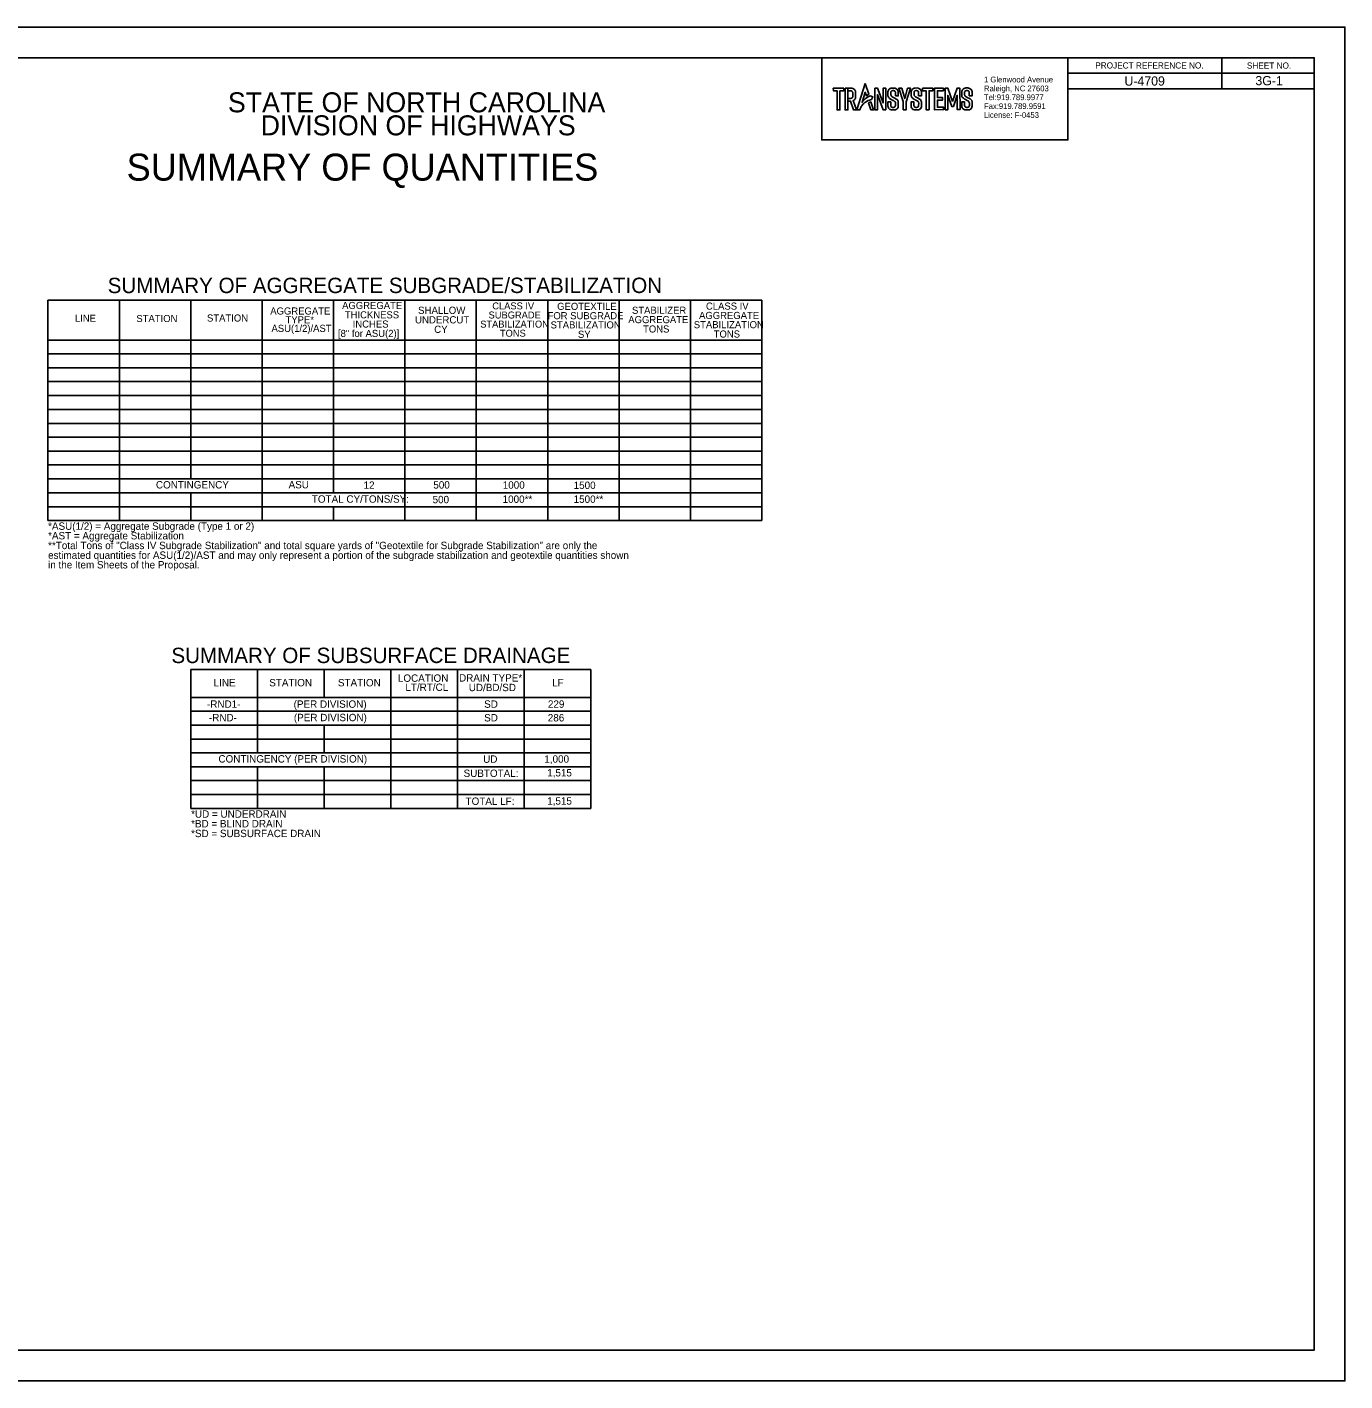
# Model space of a CAD drawing. Extents: x 573680 to 575380, y -54660 to -53560.
# Drawn here: x 574309 to 575380, y -54660 to -53560 of the extents above; entities that cross this region are included whole.
import ezdxf

# ---------------------------------------------------------------- set-up
doc = ezdxf.new("R2010")
doc.units = 0
for name, color, linetype in [('Old_Level_2', 7, 'Continuous'), ('Old_Level_58', 7, 'Continuous'), ('Prop Dimension Text', 7, 'Continuous'), ('Sheet Data Field CELL', 7, 'Continuous'), ('Sheet Plan And Profile CELL', 7, 'Continuous'), ('Sheet Plot Border Outside CELL', 7, 'Continuous'), ('Sheet Summary CELL', 7, 'Continuous'), ('Sheet Summary Combination CELL', 7, 'Continuous'), ('Sheet Summary Combination Grid CELL', 7, 'Continuous')]:
    doc.layers.add(name, color=color, linetype=linetype)

msp = doc.modelspace()

# ---------------------------------------------------------------- linework, layer by layer
at = {"layer": 'Old_Level_58'}
msp.add_lwpolyline([(574954.8, -53584.7), (575154.8, -53584.7), (575154.8, -53651.4), (574954.8, -53651.4)], close=True, dxfattribs=at)
at = {"layer": 'Sheet Plan And Profile CELL'}
for p, q in [((575279.9, -53584.8), (575279.9, -53609.8)), ((575154.8, -53597.3), (575354.9, -53597.3))]:
    msp.add_line(p, q, dxfattribs=at)
msp.add_lwpolyline([(575354.9, -53584.7), (573854.9, -53584.7), (573854.9, -54634.7), (575354.9, -54634.7)], close=True, dxfattribs=at)
at = {"layer": 'Sheet Plot Border Outside CELL'}
msp.add_lwpolyline([(573679.9, -54659.7), (575379.9, -54659.7), (575379.9, -53559.7), (573679.9, -53559.7)], close=True, dxfattribs=at)
at = {"layer": 'Sheet Summary CELL'}
for p, q in [((575279.9, -53584.8), (575279.9, -53609.8)), ((575154.8, -53597.3), (575354.9, -53597.3)), ((574604.5, -53673.5), (574604.5, -53673.5))]:
    msp.add_line(p, q, dxfattribs=at)
msp.add_lwpolyline([(575154.8, -53584.7), (575354.9, -53584.7), (575354.9, -53609.8), (575154.8, -53609.8)], close=True, dxfattribs=at)
at = {"layer": 'Sheet Summary Combination CELL'}
for p, q in [((574569.8, -54081.8), (574569.8, -54081.8)), ((574575.4, -54081.9), (574575.4, -54081.9)), ((574583.6, -54081.7), (574583.6, -54081.7)), ((574588.6, -54081.8), (574588.6, -54081.8))]:
    msp.add_line(p, q, dxfattribs=at)
at = {"layer": 'Sheet Summary Combination Grid CELL'}
for p, q in [((574326.1, -53781.7), (574906.1, -53781.7)), ((574326.1, -53781.7), (574326.1, -53960.7)), ((574384.1, -53781.7), (574384.1, -53960.7)), ((574442.1, -53781.7), (574442.1, -53926.8)), ((574500.1, -53781.7), (574500.1, -53960.7)), ((574558.1, -53781.7), (574558.1, -53938.1)), ((574616.1, -53781.7), (574616.1, -53960.7)), ((574674.1, -53781.7), (574674.1, -53960.7)), ((574732.1, -53781.7), (574732.1, -53960.7)), ((574790.1, -53781.7), (574790.1, -53960.7)), ((574848.1, -53781.7), (574848.1, -53960.7)), ((574906.1, -53781.7), (574906.1, -53960.7)), ((574326.1, -53814), (574906.1, -53814)), ((574326.1, -53825.3), (574906.1, -53825.3)), ((574326.1, -53836.6), (574906.1, -53836.6)), ((574326.1, -53847.8), (574906.1, -53847.8)), ((574326.1, -53859.1), (574580, -53859.1)), ((574326.1, -53859.1), (574906.1, -53859.1)), ((574326.1, -53870.4), (574906.1, -53870.4)), ((574326.1, -53881.7), (574906.1, -53881.7)), ((574326.1, -53893), (574906.1, -53893)), ((574326.1, -53904.3), (574906.1, -53904.3)), ((574326.1, -53915.5), (574906.1, -53915.5)), ((574326.1, -53926.8), (574906.1, -53926.8)), ((574326.1, -53938.1), (574906.1, -53938.1)), ((574442.1, -53938.1), (574442.1, -53960.7)), ((574326.1, -53949.4), (574906.1, -53949.4)), ((574558.1, -53949.4), (574558.1, -53960.7)), ((574326.1, -53960.7), (574906.1, -53960.7)), ((574442.3, -54081.8), (574767.2, -54081.8)), ((574442.3, -54081.8), (574442.3, -54194.6)), ((574496.4, -54081.8), (574496.4, -54149.5)), ((574550.6, -54081.8), (574550.6, -54104.4)), ((574604.7, -54081.8), (574604.7, -54194.6)), ((574658.9, -54081.8), (574658.9, -54194.6)), ((574713, -54081.8), (574713, -54194.6)), ((574767.2, -54081.8), (574767.2, -54194.6)), ((574442.3, -54104.4), (574767.2, -54104.4)), ((574442.3, -54115.6), (574767.2, -54115.6)), ((574442.3, -54126.9), (574767.2, -54126.9)), ((574550.6, -54126.9), (574550.6, -54149.5)), ((574442.3, -54138.2), (574767.2, -54138.2)), ((574442.3, -54149.5), (574696.2, -54149.5)), ((574442.3, -54149.5), (574767.2, -54149.5)), ((574442.3, -54149.5), (574767.2, -54149.5)), ((574442.3, -54160.8), (574767.2, -54160.8)), ((574496.4, -54160.8), (574496.4, -54194.6)), ((574550.6, -54160.8), (574550.6, -54194.6)), ((574550.6, -54160.8), (574550.6, -54194.6)), ((574442.3, -54172), (574767.2, -54172)), ((574442.3, -54183.3), (574767.2, -54183.3)), ((574442.3, -54194.6), (574767.2, -54194.6))]:
    msp.add_line(p, q, dxfattribs=at)
for points in [[(574964.1, -53609.5), (574972.6, -53609.5), (574972.6, -53611.6), (574969.5, -53611.6), (574969.5, -53627), (574967.2, -53627), (574967.2, -53611.5), (574964.2, -53611.5)], [(574973.8, -53609.5), (574976.1, -53609.5), (574976.1, -53627.1), (574973.8, -53627.1)], [(574976.1, -53611.6), (574978.5, -53611.6), (574978.8, -53611.6), (574979.2, -53611.8), (574979.5, -53612), (574979.7, -53612.3), (574979.9, -53612.6), (574980, -53612.9), (574980, -53613.5), (574980, -53615.9), (574980, -53616.3), (574979.9, -53616.7), (574979.7, -53617), (574979.5, -53617.3), (574979.3, -53617.5), (574978.9, -53617.6), (574978.5, -53617.7), (574978.2, -53617.7), (574976.1, -53617.7), (574976.1, -53619.8), (574978.2, -53619.8), (574980.6, -53627), (574983, -53627), (574980.3, -53619.4), (574980.7, -53619.3), (574981.3, -53618.9), (574981.7, -53618.4), (574982.1, -53617.7), (574982.3, -53617.1), (574982.3, -53616.9), (574982.3, -53612.3), (574982.1, -53611.6), (574981.8, -53610.9), (574981.4, -53610.4), (574980.7, -53610), (574980, -53609.7), (574979.3, -53609.5), (574978.9, -53609.5), (574976.1, -53609.5)], [(574990.1, -53605.6), (574983.4, -53627), (574985.7, -53627), (574986, -53626.1), (574986.6, -53625), (574986.9, -53624.3), (574987.3, -53623.8), (574987.8, -53623), (574988.1, -53622.6), (574988.5, -53622.2), (574988.9, -53621.8), (574989.4, -53621.3), (574989.8, -53621), (574990.2, -53620.7), (574990.8, -53620.4), (574991.2, -53620.1), (574992.5, -53619.5), (574993.5, -53619.1), (574995.1, -53618.5), (574996.2, -53616.4), (574994.1, -53615.5), (574992.4, -53616.3), (574991.1, -53617.2), (574990.1, -53618), (574989.6, -53618.5), (574989, -53619), (574988.5, -53619.6), (574988.1, -53620), (574987.7, -53620.7), (574987.5, -53621), (574990.1, -53612.7), (574991.1, -53615.5), (574993, -53614.3)], [(574997.9, -53609.5), (574997.9, -53626.9), (575000.1, -53626.9), (575000.1, -53614.6), (575004.6, -53626.9), (575006.8, -53626.9), (575006.8, -53609.4), (575004.6, -53609.4), (575004.6, -53621.4), (575000.2, -53609.5)], [(575014.6, -53615.6), (575016.9, -53615.6), (575016.9, -53612.2), (575016.7, -53611.4), (575016.4, -53610.9), (575016.1, -53610.5), (575015.7, -53610.1), (575015.3, -53609.8), (575014.9, -53609.7), (575014.9, -53609.7), (575014.4, -53609.5), (575013.9, -53609.3), (575013.6, -53609.3), (575011.9, -53609.3), (575011.3, -53609.4), (575010.9, -53609.5), (575010.4, -53609.7), (575010, -53609.9), (575009.6, -53610.2), (575009.3, -53610.5), (575009.1, -53610.9), (575008.9, -53611.3), (575008.6, -53612), (575008.6, -53612.5), (575008.6, -53615.7), (575008.7, -53616.1), (575008.9, -53616.6), (575009.2, -53617), (575009.5, -53617.3), (575009.9, -53617.7), (575010.4, -53618), (575010.7, -53618.3), (575011.2, -53618.5), (575011.7, -53618.7), (575012, -53619), (575012.5, -53619.3), (575013, -53619.5), (575013.4, -53619.7), (575013.9, -53620.1), (575014.2, -53620.3), (575014.4, -53620.6), (575014.6, -53621.1), (575014.7, -53621.4), (575014.6, -53623.6), (575014.5, -53624.1), (575014.2, -53624.5), (575013.9, -53624.8), (575013.6, -53625), (575013.2, -53625), (575012.3, -53625.1), (575011.9, -53625), (575011.6, -53624.8), (575011.3, -53624.6), (575011.1, -53624.2), (575011, -53623.9), (575010.9, -53623.6), (575010.8, -53620.5), (575008.5, -53620.6), (575008.5, -53624.3), (575008.7, -53624.5), (575008.9, -53625.4), (575009.1, -53625.7), (575009.4, -53626), (575009.7, -53626.4), (575010, -53626.6), (575010.5, -53626.8), (575010.6, -53626.8), (575011.1, -53627), (575011.6, -53627.1), (575012, -53627.1), (575014.1, -53627.1), (575014.7, -53626.9), (575015.6, -53626.5), (575015.8, -53626.4), (575016.5, -53625.6), (575016.8, -53624.8), (575016.9, -53624.1), (575016.9, -53620.7), (575016.9, -53620.2), (575016.8, -53619.9), (575016.6, -53619.5), (575016, -53618.7), (575015.3, -53618.2), (575014.3, -53617.6), (575013.6, -53617.2), (575012.1, -53616.4), (575011.4, -53615.8), (575011.1, -53615.4), (575011, -53615.1), (575010.9, -53614.8), (575010.9, -53612.4), (575011.1, -53612.2), (575011.2, -53611.9), (575011.4, -53611.8), (575011.6, -53611.6), (575011.9, -53611.4), (575012.1, -53611.3), (575012.3, -53611.4), (575012.3, -53611.3), (575013.2, -53611.3), (575013.5, -53611.4), (575013.8, -53611.5), (575014.1, -53611.6), (575014.2, -53611.8), (575014.4, -53612.1), (575014.5, -53612.4), (575014.6, -53612.7), (575014.6, -53613)], [(575019.9, -53609.5), (575017.3, -53609.5), (575020.9, -53620.3), (575021, -53626.9), (575023.4, -53626.9), (575023.3, -53620.4), (575027, -53609.4), (575024.5, -53609.5), (575022.2, -53617.8)], [(575033.5, -53615.6), (575035.8, -53615.6), (575035.8, -53612.1), (575035.6, -53611.4), (575035.3, -53610.8), (575035, -53610.4), (575034.6, -53610.1), (575034.2, -53609.8), (575033.7, -53609.6), (575033.7, -53609.6), (575033.3, -53609.4), (575032.8, -53609.3), (575032.5, -53609.2), (575030.7, -53609.3), (575030.2, -53609.4), (575029.8, -53609.5), (575029.3, -53609.7), (575028.9, -53609.9), (575028.5, -53610.2), (575028.2, -53610.5), (575027.9, -53610.9), (575027.7, -53611.3), (575027.5, -53612), (575027.4, -53612.5), (575027.4, -53615.6), (575027.6, -53616.1), (575027.8, -53616.6), (575028.1, -53617), (575028.4, -53617.3), (575028.8, -53617.7), (575029.3, -53618), (575029.6, -53618.2), (575030, -53618.5), (575030.5, -53618.7), (575030.9, -53619), (575031.4, -53619.2), (575031.9, -53619.5), (575032.3, -53619.7), (575032.7, -53620), (575033.1, -53620.3), (575033.3, -53620.6), (575033.5, -53621.1), (575033.6, -53621.3), (575033.5, -53623.6), (575033.4, -53624.1), (575033.1, -53624.5), (575032.8, -53624.8), (575032.4, -53624.9), (575032.1, -53625), (575031.1, -53625), (575030.8, -53624.9), (575030.5, -53624.8), (575030.1, -53624.6), (575030, -53624.2), (575029.9, -53623.9), (575029.7, -53623.6), (575029.7, -53620.5), (575027.4, -53620.5), (575027.4, -53624.2), (575027.5, -53624.5), (575027.8, -53625.4), (575028, -53625.7), (575028.2, -53626), (575028.6, -53626.4), (575028.9, -53626.6), (575029.4, -53626.8), (575029.5, -53626.8), (575029.9, -53627), (575030.5, -53627.1), (575030.9, -53627.1), (575033, -53627), (575033.6, -53626.9), (575034.4, -53626.5), (575034.7, -53626.4), (575035.3, -53625.6), (575035.7, -53624.8), (575035.8, -53624.1), (575035.8, -53620.7), (575035.8, -53620.2), (575035.6, -53619.8), (575035.4, -53619.5), (575034.9, -53618.7), (575034.2, -53618.2), (575033.2, -53617.6), (575032.5, -53617.1), (575031, -53616.4), (575030.3, -53615.8), (575029.9, -53615.4), (575029.8, -53615.1), (575029.8, -53614.8), (575029.8, -53612.4), (575029.9, -53612.1), (575030.1, -53611.9), (575030.2, -53611.7), (575030.5, -53611.5), (575030.7, -53611.4), (575031, -53611.3), (575031.1, -53611.4), (575031.2, -53611.3), (575032.1, -53611.3), (575032.4, -53611.4), (575032.7, -53611.5), (575032.9, -53611.6), (575033.1, -53611.8), (575033.3, -53612.1), (575033.4, -53612.4), (575033.4, -53612.6), (575033.4, -53612.9)], [(575036.6, -53609.4), (575045.1, -53609.4), (575045.1, -53611.5), (575042, -53611.5), (575042, -53626.9), (575039.6, -53626.9), (575039.6, -53611.4), (575036.6, -53611.4)], [(575053.7, -53609.4), (575046.3, -53609.4), (575046.3, -53626.9), (575053.8, -53626.8), (575053.8, -53624.9), (575048.7, -53624.9), (575048.7, -53619), (575052.9, -53619), (575052.9, -53617), (575048.7, -53617), (575048.7, -53611.5), (575053.7, -53611.5)], [(575061.1, -53620.3), (575057.2, -53609.3), (575055, -53609.5), (575055.1, -53626.9), (575057.2, -53626.9), (575057.2, -53615.2), (575060.4, -53624.2), (575061.8, -53624.2), (575064.9, -53615.1), (575064.9, -53626.8), (575067.2, -53626.8), (575067.1, -53609.4), (575064.8, -53609.4)], [(575074.6, -53615.6), (575076.9, -53615.6), (575076.9, -53612.1), (575076.7, -53611.4), (575076.4, -53610.8), (575076.1, -53610.4), (575075.7, -53610.1), (575075.3, -53609.8), (575074.9, -53609.6), (575074.9, -53609.6), (575074.4, -53609.4), (575073.9, -53609.3), (575073.6, -53609.2), (575071.9, -53609.2), (575071.3, -53609.3), (575070.9, -53609.4), (575070.4, -53609.7), (575070, -53609.9), (575069.6, -53610.1), (575069.3, -53610.5), (575069.1, -53610.8), (575068.9, -53611.2), (575068.6, -53611.9), (575068.6, -53612.4), (575068.6, -53615.6), (575068.7, -53616.1), (575068.9, -53616.6), (575069.2, -53617), (575069.5, -53617.3), (575070, -53617.6), (575070.4, -53618), (575070.7, -53618.2), (575071.2, -53618.4), (575071.7, -53618.7), (575072, -53618.9), (575072.5, -53619.2), (575073, -53619.5), (575073.4, -53619.7), (575073.9, -53620), (575074.2, -53620.3), (575074.4, -53620.5), (575074.6, -53621), (575074.7, -53621.3), (575074.7, -53623.5), (575074.5, -53624), (575074.2, -53624.5), (575073.9, -53624.7), (575073.6, -53624.9), (575073.2, -53625), (575072.3, -53625), (575071.9, -53624.9), (575071.6, -53624.7), (575071.3, -53624.5), (575071.1, -53624.2), (575071, -53623.8), (575070.9, -53623.6), (575070.8, -53620.5), (575068.5, -53620.5), (575068.5, -53624.2), (575068.7, -53624.5), (575068.9, -53625.4), (575069.1, -53625.6), (575069.4, -53626), (575069.7, -53626.3), (575070.1, -53626.5), (575070.5, -53626.7), (575070.6, -53626.8), (575071.1, -53627), (575071.6, -53627), (575072, -53627.1), (575074.1, -53627), (575074.7, -53626.9), (575075.6, -53626.5), (575075.8, -53626.4), (575076.5, -53625.6), (575076.8, -53624.8), (575077, -53624.1), (575076.9, -53620.6), (575076.9, -53620.2), (575076.8, -53619.8), (575076.6, -53619.4), (575076, -53618.7), (575075.3, -53618.1), (575074.3, -53617.5), (575073.6, -53617.1), (575072.1, -53616.3), (575071.4, -53615.8), (575071.1, -53615.4), (575071, -53615.1), (575070.9, -53614.8), (575070.9, -53612.4), (575071.1, -53612.1), (575071.2, -53611.8), (575071.4, -53611.7), (575071.6, -53611.5), (575071.9, -53611.4), (575072.1, -53611.3), (575072.3, -53611.3), (575072.3, -53611.2), (575073.2, -53611.3), (575073.5, -53611.4), (575073.8, -53611.5), (575074.1, -53611.6), (575074.2, -53611.8), (575074.4, -53612.1), (575074.5, -53612.3), (575074.6, -53612.6), (575074.6, -53612.9)], [(574992.7, -53621.3), (574994.6, -53620.6), (574996.9, -53627), (574994.8, -53626.9)]]:
    msp.add_lwpolyline(points, close=True, dxfattribs=at)

# ---------------------------------------------------------------- texts
at = {"layer": 'Old_Level_2'}
for s, p in [('1 Glenwood Avenue', (575086.6, -53604.7)), ('Raleigh, NC 27603', (575086.6, -53611.9)), ('Tel:919.789.9977 ', (575086.6, -53619.1)), ('Fax:919.789.9591', (575086.6, -53626.3)), ('License: F-0453', (575086.6, -53633.5))]:
    msp.add_text(s, height=4.658, rotation=360, dxfattribs=at).set_placement(p)
at = {"layer": 'Prop Dimension Text'}
for s, p in [('ASU', (574521.6, -53934.5)), ('12', (574582.5, -53934.9)), ('500', (574639.2, -53934.7)), ('1000', (574695.6, -53934.8)), ('1500', (574753.2, -53935)), ('500', (574638.6, -53946.6)), ('1000**', (574695.5, -53946.3)), ('1500**', (574753.2, -53946.3))]:
    msp.add_text(s, height=6, dxfattribs=at).set_placement(p)
at = {"layer": 'Sheet Data Field CELL'}
for s, p in [('U-4709', (575200.7, -53607.3)), ('3G-1', (575307.1, -53607))]:
    msp.add_text(s, height=7.5, dxfattribs=at).set_placement(p)
at = {"layer": 'Sheet Plan And Profile CELL'}
for s, p in [('PROJECT REFERENCE NO.', (575177, -53593.4)), ('SHEET NO.', (575300.2, -53593.5))]:
    msp.add_text(s, height=5, rotation=360, dxfattribs=at).set_placement(p)
at = {"layer": 'Sheet Summary CELL'}
for s, height, p in [('PROJECT REFERENCE NO.', 5, (575177, -53593.4)), ('SHEET NO.', 5, (575300.2, -53593.5)), ('STATE OF NORTH CAROLINA', 16.25, (574472.3, -53629)), ('DIVISION OF HIGHWAYS', 16.25, (574498.9, -53647.7)), ('SUMMARY OF QUANTITIES', 21.95, (574390, -53684.5))]:
    msp.add_text(s, height=height, dxfattribs=at).set_placement(p)
at = {"layer": 'Sheet Summary Combination CELL'}
for s, p in [('SUMMARY OF AGGREGATE SUBGRADE/STABILIZATION', (574374.6, -53775.9)), ('SUMMARY OF SUBSURFACE DRAINAGE', (574426.4, -54076.5))]:
    msp.add_text(s, height=12.5, rotation=0.0119, dxfattribs=at).set_placement(p)
for s, height, p in [('AGGREGATE', 5.76, (574506.7, -53793.3)), ('LINE', 5.76, (574348, -53799.2)), ('STATION', 5.76, (574397.9, -53799.4)), ('STATION', 5.76, (574455.3, -53799)), ('TYPE*', 5.76, (574519.1, -53800.4)), ('ASU(1/2)/AST', 5.762, (574507.7, -53807.4)), ('CONTINGENCY ', 6, (574413.8, -53934.6)), ('TOTAL CY/TONS/SY:', 6, (574540.5, -53946.2)), ('*ASU(1/2) = Aggregate Subgrade (Type 1 or 2)', 6, (574326.2, -53968.2)), ('*AST = Aggregate Stabilization', 6, (574326.2, -53976)), ('**Total Tons of "Class IV Subgrade Stabilization" and total square yards of "Geotextile for Subgrade Stabilization" are only the', 6, (574326.2, -53983.9)), ('estimated quantities for ASU(1/2)/AST and may only represent a portion of the subgrade stabilization and geotextile quantities shown', 6, (574326.2, -53991.8)), ('in the Item Sheets of the Proposal.', 6, (574326.2, -53999.6)), ('LOCATION', 6, (574610.4, -54091.7)), ('LINE', 6, (574460.7, -54095.4)), ('STATION', 6, (574505.9, -54095.4)), ('STATION', 6, (574561.7, -54095.4)), ('LT/RT/CL', 6, (574616.5, -54099.1)), ('-RND1-', 6, (574455.3, -54112.8)), ('(PER DIVISION)', 6, (574525.7, -54112.8)), ('SD', 6, (574680.5, -54112.8)), ('229', 6, (574732.3, -54112.8)), ('-RND-', 6, (574456.9, -54123.8)), ('(PER DIVISION)', 6, (574525.9, -54123.7)), ('SD', 6, (574680.5, -54123.9)), ('286', 6, (574732.2, -54123.9)), ('CONTINGENCY (PER DIVISION)', 6, (574464.6, -54157.3)), ('UD', 6, (574679.7, -54157.5)), ('1,000', 6, (574729.4, -54157.4)), ('SUBTOTAL:', 6, (574663.8, -54169)), ('1,515', 6, (574731.7, -54168.6)), ('TOTAL LF:', 6, (574665.4, -54191.7)), ('1,515', 6, (574731.7, -54191.5)), ('*UD = UNDERDRAIN', 6, (574442.4, -54202.1)), ('*BD = BLIND DRAIN', 6, (574442.4, -54210)), ('*SD = SUBSURFACE DRAIN', 6, (574442.4, -54217.9))]:
    msp.add_text(s, height=height, dxfattribs=at).set_placement(p)
at = {"layer": 'Sheet Summary Combination Grid CELL'}
for s, height, p in [('AGGREGATE', 5.76, (574565.1, -53788.8)), ('SHALLOW', 5.88, (574626.8, -53792.8)), ('CLASS IV', 5.65, (574687.1, -53789.1)), ('GEOTEXTILE', 5.76, (574739.8, -53789.5)), ('STABILIZER', 5.76, (574800.6, -53792.7)), ('CLASS IV', 5.76, (574860.7, -53789.3)), ('THICKNESS', 5.76, (574567.3, -53796.4)), ('INCHES', 5.76, (574573.7, -53803.9)), ('UNDERCUT', 5.88, (574624.3, -53800.5)), ('STABILIZATION', 5.647, (574677.3, -53803.9)), ('SUBGRADE', 5.65, (574684.1, -53796.5)), ('FOR SUBGRADE', 5.762, (574732, -53797.1)), ('STABILIZATION', 5.762, (574734.5, -53804.6)), ('AGGREGATE', 5.76, (574797.6, -53800.3)), ('STABILIZATION', 5.762, (574850.8, -53804.4)), ('AGGREGATE', 5.76, (574855.1, -53796.9)), ('[8" for ASU(2)]', 5.762, (574561.7, -53811.5)), ('CY', 5.88, (574639.9, -53808.2)), ('TONS', 5.65, (574693.3, -53811.3)), ('SY', 5.76, (574756.7, -53812.2)), ('TONS', 5.76, (574809.6, -53807.9)), ('TONS', 5.76, (574867, -53812)), ('DRAIN TYPE*', 6, (574660.1, -54091.5)), ('UD/BD/SD', 6, (574668, -54099.3)), ('LF', 6, (574735.7, -54095.4))]:
    msp.add_text(s, height=height, dxfattribs=at).set_placement(p)

doc.saveas('drawing.dxf')
